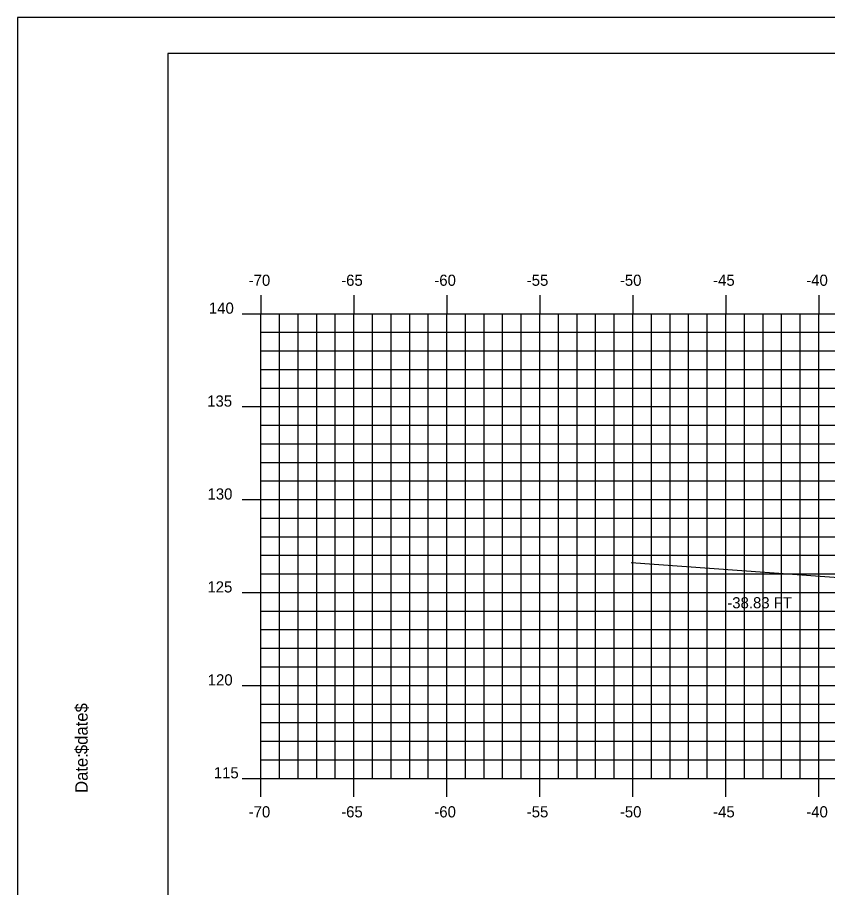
# Model space of a CAD drawing. Extents: x 1145638 to 1145808, y 608981 to 609091.
# Drawn here: x 1145637.55 to 1145681.12, y 609044.46 to 609091.28 of the extents above; entities that cross this region are included whole.
import ezdxf

# ---------------------------------------------------------------- set-up
doc = ezdxf.new("R2010")
doc.units = 0
for name, color, linetype in [('BORDER', 7, 'Continuous'), ('D_Text_Standard', 7, 'Continuous'), ('H_V ANNOTATION', 7, 'Continuous'), ('MAJOR', 7, 'Continuous'), ('MINOR', 7, 'Continuous'), ('PLOT BOUNDARY', 7, 'Continuous'), ('S_Roadway_Centerline', 7, 'Continuous')]:
    doc.layers.add(name, color=color, linetype=linetype)

msp = doc.modelspace()

# ---------------------------------------------------------------- linework, layer by layer
at = {"layer": 'BORDER'}
msp.add_lwpolyline([(1145645.645, 608984.335), (1145805.645, 608984.335), (1145805.645, 609089.335), (1145645.645, 609089.335)], close=True, dxfattribs=at)
at = {"layer": 'MAJOR'}
for p, q in [((1145650.645, 609076.337), (1145650.645, 609075.335)), ((1145655.645, 609076.337), (1145655.645, 609075.335)), ((1145660.645, 609076.337), (1145660.645, 609075.335)), ((1145665.645, 609076.337), (1145665.645, 609075.335)), ((1145670.645, 609076.337), (1145670.645, 609075.335)), ((1145675.645, 609076.337), (1145675.645, 609075.335)), ((1145680.645, 609076.337), (1145680.645, 609075.335)), ((1145649.643, 609075.335), (1145650.645, 609075.335)), ((1145650.645, 609075.335), (1145790.645, 609075.335)), ((1145650.645, 609050.335), (1145650.645, 609075.335)), ((1145650.645, 609050.335), (1145650.645, 609075.335)), ((1145650.645, 609075.335), (1145790.645, 609075.335)), ((1145655.645, 609050.335), (1145655.645, 609075.335)), ((1145660.645, 609050.335), (1145660.645, 609075.335)), ((1145665.645, 609050.335), (1145665.645, 609075.335)), ((1145670.645, 609050.335), (1145670.645, 609075.335)), ((1145675.645, 609050.335), (1145675.645, 609075.335)), ((1145680.645, 609050.335), (1145680.645, 609075.335)), ((1145649.643, 609070.335), (1145650.645, 609070.335)), ((1145650.645, 609070.335), (1145790.645, 609070.335)), ((1145649.643, 609065.335), (1145650.645, 609065.335)), ((1145650.645, 609065.335), (1145790.645, 609065.335)), ((1145649.643, 609060.335), (1145650.645, 609060.335)), ((1145650.645, 609060.335), (1145790.645, 609060.335)), ((1145649.643, 609055.335), (1145650.645, 609055.335)), ((1145650.645, 609055.335), (1145790.645, 609055.335)), ((1145649.643, 609050.335), (1145650.645, 609050.335)), ((1145650.645, 609050.335), (1145790.645, 609050.335)), ((1145650.645, 609050.335), (1145790.645, 609050.335)), ((1145650.645, 609049.333), (1145650.645, 609050.335)), ((1145655.645, 609049.333), (1145655.645, 609050.335)), ((1145660.645, 609049.333), (1145660.645, 609050.335)), ((1145665.645, 609049.333), (1145665.645, 609050.335)), ((1145670.645, 609049.333), (1145670.645, 609050.335)), ((1145675.645, 609049.333), (1145675.645, 609050.335)), ((1145680.645, 609049.333), (1145680.645, 609050.335))]:
    msp.add_line(p, q, dxfattribs=at)
at = {"layer": 'MINOR'}
for p, q in [((1145651.645, 609050.335), (1145651.645, 609075.335)), ((1145652.645, 609050.335), (1145652.645, 609075.335)), ((1145653.645, 609050.335), (1145653.645, 609075.335)), ((1145654.645, 609050.335), (1145654.645, 609075.335)), ((1145656.645, 609050.335), (1145656.645, 609075.335)), ((1145657.645, 609050.335), (1145657.645, 609075.335)), ((1145658.645, 609050.335), (1145658.645, 609075.335)), ((1145659.645, 609050.335), (1145659.645, 609075.335)), ((1145661.645, 609050.335), (1145661.645, 609075.335)), ((1145662.645, 609050.335), (1145662.645, 609075.335)), ((1145663.645, 609050.335), (1145663.645, 609075.335)), ((1145664.645, 609050.335), (1145664.645, 609075.335)), ((1145666.645, 609050.335), (1145666.645, 609075.335)), ((1145667.645, 609050.335), (1145667.645, 609075.335)), ((1145668.645, 609050.335), (1145668.645, 609075.335)), ((1145669.645, 609050.335), (1145669.645, 609075.335)), ((1145671.645, 609050.335), (1145671.645, 609075.335)), ((1145672.645, 609050.335), (1145672.645, 609075.335)), ((1145673.645, 609050.335), (1145673.645, 609075.335)), ((1145674.645, 609050.335), (1145674.645, 609075.335)), ((1145676.645, 609050.335), (1145676.645, 609075.335)), ((1145677.645, 609050.335), (1145677.645, 609075.335)), ((1145678.645, 609050.335), (1145678.645, 609075.335)), ((1145679.645, 609050.335), (1145679.645, 609075.335)), ((1145650.645, 609074.335), (1145790.645, 609074.335)), ((1145650.645, 609074.335), (1145651.647, 609074.335)), ((1145650.645, 609073.335), (1145790.645, 609073.335)), ((1145650.645, 609073.335), (1145651.647, 609073.335)), ((1145650.645, 609072.335), (1145790.645, 609072.335)), ((1145650.645, 609072.335), (1145651.647, 609072.335)), ((1145650.645, 609071.335), (1145790.645, 609071.335)), ((1145650.645, 609071.335), (1145651.647, 609071.335)), ((1145650.645, 609069.335), (1145790.645, 609069.335)), ((1145650.645, 609069.335), (1145651.647, 609069.335)), ((1145650.645, 609068.335), (1145790.645, 609068.335)), ((1145650.645, 609068.335), (1145651.647, 609068.335)), ((1145650.645, 609067.335), (1145790.645, 609067.335)), ((1145650.645, 609067.335), (1145651.647, 609067.335)), ((1145650.645, 609066.335), (1145790.645, 609066.335)), ((1145650.645, 609066.335), (1145651.647, 609066.335)), ((1145650.645, 609064.335), (1145790.645, 609064.335)), ((1145650.645, 609064.335), (1145651.647, 609064.335)), ((1145650.645, 609063.335), (1145790.645, 609063.335)), ((1145650.645, 609063.335), (1145651.647, 609063.335)), ((1145650.645, 609062.335), (1145790.645, 609062.335)), ((1145650.645, 609062.335), (1145651.647, 609062.335)), ((1145650.645, 609061.335), (1145790.645, 609061.335)), ((1145650.645, 609061.335), (1145651.647, 609061.335)), ((1145650.645, 609059.335), (1145790.645, 609059.335)), ((1145650.645, 609059.335), (1145651.647, 609059.335)), ((1145650.645, 609058.335), (1145790.645, 609058.335)), ((1145650.645, 609058.335), (1145651.647, 609058.335)), ((1145650.645, 609057.335), (1145790.645, 609057.335)), ((1145650.645, 609057.335), (1145651.647, 609057.335)), ((1145650.645, 609056.335), (1145790.645, 609056.335)), ((1145650.645, 609056.335), (1145651.647, 609056.335)), ((1145650.645, 609054.335), (1145790.645, 609054.335)), ((1145650.645, 609054.335), (1145651.647, 609054.335)), ((1145650.645, 609053.335), (1145790.645, 609053.335)), ((1145650.645, 609053.335), (1145651.647, 609053.335)), ((1145650.645, 609052.335), (1145790.645, 609052.335)), ((1145650.645, 609052.335), (1145651.647, 609052.335)), ((1145650.645, 609051.335), (1145790.645, 609051.335)), ((1145650.645, 609051.335), (1145651.647, 609051.335))]:
    msp.add_line(p, q, dxfattribs=at)
at = {"layer": 'PLOT BOUNDARY'}
msp.add_lwpolyline([(1145637.552, 608981.276), (1145807.552, 608981.276), (1145807.552, 609091.276), (1145637.552, 609091.276)], close=True, dxfattribs=at)
at = {"layer": 'S_Roadway_Centerline'}
msp.add_lwpolyline([(1145670.563, 609061.952), (1145685.175, 609060.891), (1145685.737, 609060.851), (1145688.296, 609060.867), (1145697.073, 609061.142), (1145704.489, 609062.703), (1145705.144, 609062.915), (1145707.28, 609063.094), (1145707.355, 609063.105), (1145707.651, 609063.114), (1145718.66, 609063.546), (1145728.46, 609063.36), (1145729.217, 609063.34), (1145732.934, 609062.767), (1145733.208, 609062.71), (1145735.659, 609061.739), (1145744.076, 609058.7), (1145752.065, 609058.73), (1145764.42, 609057.896), (1145765.193, 609057.913)], dxfattribs=at)

# ---------------------------------------------------------------- texts
at = {"layer": 'BORDER'}
for s, p in [('$date$', (1145641.33, 609051.64)), ('Date:', (1145641.33, 609049.552))]:
    msp.add_text(s, height=0.6696, rotation=90, dxfattribs=at).set_placement(p)
at = {"layer": 'D_Text_Standard'}
msp.add_text('-38.83 FT', height=0.6, dxfattribs=at).set_placement((1145675.725, 609059.483))
at = {"layer": 'H_V ANNOTATION'}
for s, p in [('-70', (1145649.987, 609076.835)), ('-65', (1145654.963, 609076.835)), ('-60', (1145659.971, 609076.835)), ('-55', (1145664.941, 609076.835)), ('-50', (1145669.949, 609076.835)), ('-45', (1145674.963, 609076.835)), ('-40', (1145679.971, 609076.835)), ('140', (1145647.85, 609075.335)), ('135', (1145647.759, 609070.335)), ('130', (1145647.775, 609065.335)), ('125', (1145647.77, 609060.335)), ('120', (1145647.786, 609055.335)), ('115', (1145648.112, 609050.335)), ('-70', (1145649.987, 609048.235)), ('-65', (1145654.963, 609048.235)), ('-60', (1145659.971, 609048.235)), ('-55', (1145664.941, 609048.235)), ('-50', (1145669.949, 609048.235)), ('-45', (1145674.963, 609048.235)), ('-40', (1145679.971, 609048.235))]:
    msp.add_text(s, height=0.6, dxfattribs=at).set_placement(p)
at = {"layer": 'MAJOR'}
msp.add_text('-', height=0.006, dxfattribs=at).set_placement((1145650.641, 609050.335))

doc.saveas('drawing.dxf')
